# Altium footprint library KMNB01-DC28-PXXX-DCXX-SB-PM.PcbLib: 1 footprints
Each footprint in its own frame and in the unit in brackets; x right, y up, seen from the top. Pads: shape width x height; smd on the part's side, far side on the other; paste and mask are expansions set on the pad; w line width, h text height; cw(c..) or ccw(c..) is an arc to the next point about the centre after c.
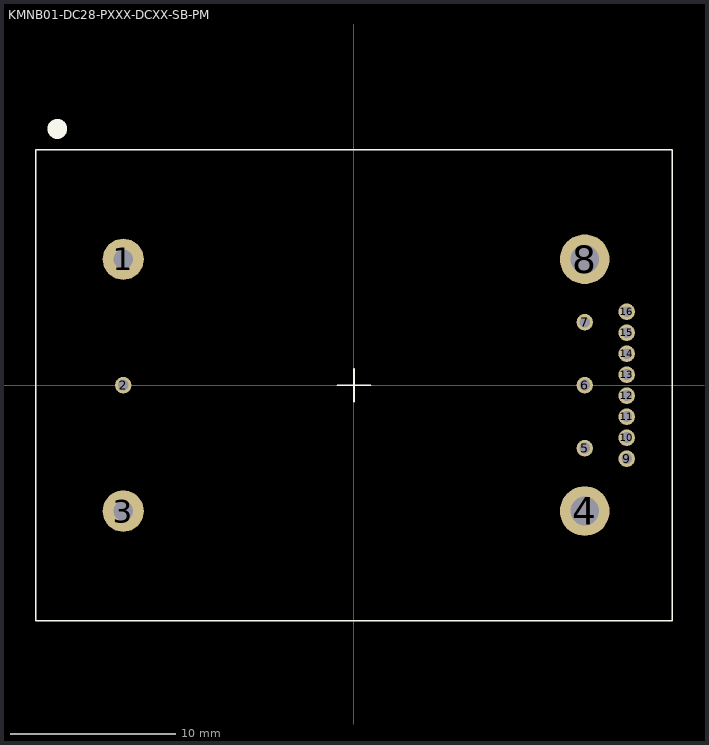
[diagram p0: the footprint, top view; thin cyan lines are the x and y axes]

## KMNB01-DC28-PXXX-DCXX-SB-PM [mm] "KMNB01-DC28-PXXX-DCXX-SB-PM"
height 12.7
pads (16):
  round 2.5 hole 1.2: 1(-13.96,7.62) 3(-13.96,-7.62)
  round 1 hole 0.66: 2(-13.96,0) 5(13.96,-3.81) 6(13.96,0) 7(13.96,3.81) 9(16.5,-4.445) 10(16.5,-3.175) 11(16.5,-1.905) 12(16.5,-0.635) 13(16.5,0.635) 14(16.5,1.905) 15(16.5,3.175) 16(16.5,4.445)
  round 3 hole 1.75: 4(13.96,-7.62) 8(13.96,7.62)
Top Overlay:
  circle w1: c-17.95,15.505 r0.1
  lines w0.1: -1,0 0,0 ; 0,-1 0,0 ; 0,1 0,0 ; 1,0 0,0 ; -19.25,-14.25 19.25,-14.25 19.25,14.25 -19.25,14.25 -19.25,-14.25
Bottom Overlay:
  circle w1: c-17.95,12.495 r0.1
  text "-VOUT" at 17.9,-9.883 h0.7
  text "-SENSE" at 17.9,-5.983 h0.7
  text "TRIM" at 17.9,-1.225 h0.7
  text "+SENSE" at 17.9,2.017 h0.7
  text "+VOUT" at 17.9,6.617 h0.7
  text "+VIN" at -18.6,6.376 h0.7
  text "ON/OFF" at -18.6,-1.965 h0.7
  text "-VIN" at -18.6,-8.849 h0.7
3D body "KMNB01-PM.STEP": height 12.91, standoff -5.39, extent -18.993,-13.996 19.007,14.004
